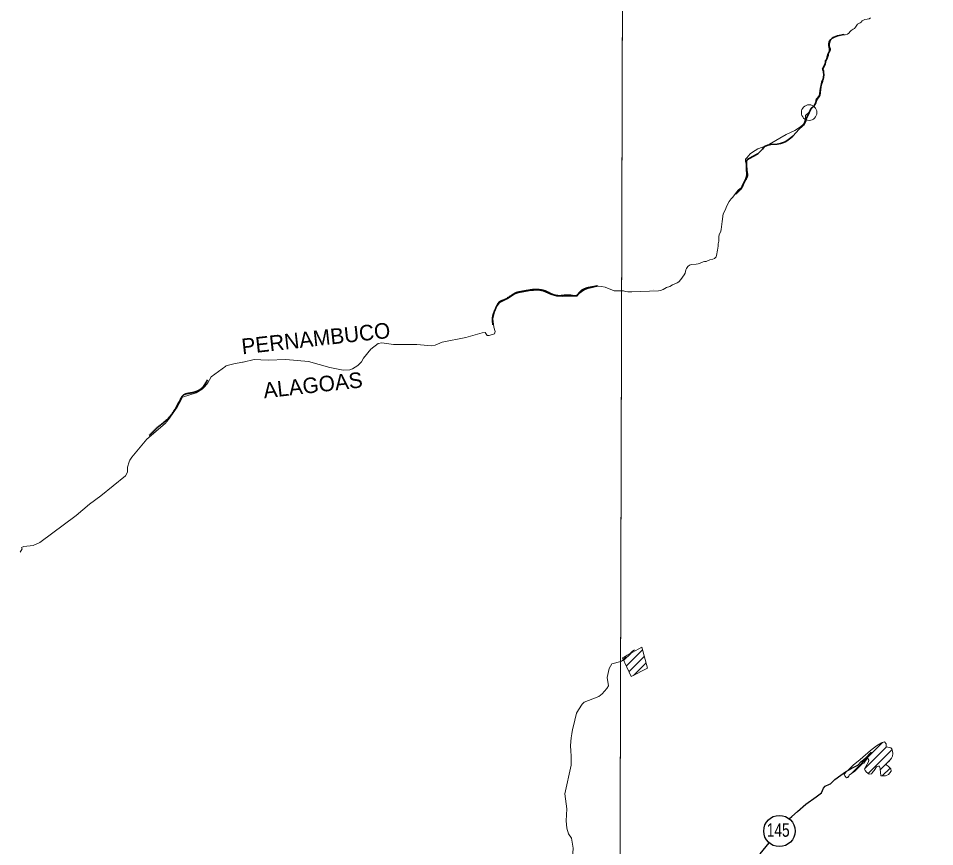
# Model space of a CAD drawing. Extents: x -1643653 to 4543381, y 1624270 to 13878484.
# Drawn here: x 582541 to 587242, y 8914739 to 8918990 of the extents above; entities that cross this region are included whole.
import ezdxf
from ezdxf.enums import TextEntityAlignment as Align

# ---------------------------------------------------------------- set-up
doc = ezdxf.new("R2010")
doc.units = 0
doc.header["$LTSCALE"] = 160
doc.header["$PDMODE"] = 32
doc.header["$PDSIZE"] = 80
doc.linetypes.add('LONG_DASH_SHORT_DASH', pattern=[9.9, 6, -1.2, 1.5, -1.2])
doc.layers.add('6', color=7, linetype='Continuous', lineweight=13)
doc.layers.add('60', color=7, linetype='Continuous', lineweight=13)

msp = doc.modelspace()

# ---------------------------------------------------------------- linework, layer by layer
at = {"layer": '6', "linetype": 'LONG_DASH_SHORT_DASH', "lineweight": 35}
msp.add_line((585799, 8917597.9), (585799.3, 8917597.8), dxfattribs=at)
at = {"layer": '6'}
for p, q in [((585646.2, 8915694.7), (585684.3, 8915732.9)), ((585659.8, 8915665.9), (585742.7, 8915748.8)), ((585654.5, 8915713.5), (585659, 8915718.1)), ((585673.4, 8915637.1), (585751.8, 8915715.5)), ((585696.2, 8915617.4), (585761, 8915682.2)), ((586813.8, 8915113.8), (586974.3, 8915274.2)), ((586882.8, 8915140.3), (586994.4, 8915251.9)), ((586900.1, 8915115.2), (587023, 8915238.1)), ((586961.6, 8915134.2), (587014.3, 8915187)), ((586972, 8915102.2), (587012.5, 8915142.8)), ((586794.2, 8915094.1), (586800.9, 8915100.8))]:
    msp.add_line(p, q, dxfattribs=at)
for points in [[(585656.3, 8924738.8), (585614.8, 8909969.8), (585573.6, 8896026.7)], [(586679.6, 8918760.5), (586680.3, 8918772.5), (586692.5, 8918786.5), (586696.8, 8918798.9), (586696.9, 8918809.3), (586697.7, 8918812.7), (586699.3, 8918815.3), (586704.2, 8918820.1), (586707.7, 8918826.9), (586707.4, 8918834.5), (586702.6, 8918847.7), (586701.8, 8918857.5), (586703.1, 8918864.1), (586709.7, 8918881.3), (586721, 8918893.5), (586725.9, 8918895.7), (586766.1, 8918904.9), (586782.2, 8918905.1), (586794.3, 8918909.1), (586801.8, 8918914.7), (586808.8, 8918923.3), (586813, 8918927.3), (586824.3, 8918933.9), (586830.1, 8918938.5), (586834.8, 8918944.1), (586841.9, 8918955.9), (586845.8, 8918960.3), (586848.8, 8918962.4), (586859.7, 8918966.8), (586863.7, 8918970.4), (586869.3, 8918977.4), (586877.2, 8918981.7), (586883.6, 8918984.1), (586895.7, 8918985.2), (586905.7, 8918987.4), (586911.9, 8918992.7)], [(586136.8, 8917879.9), (586143.9, 8917898.3), (586146.5, 8917907.1), (586150.7, 8917947.5), (586156.3, 8917986.5), (586166.2, 8918006.3), (586175.4, 8918028.7), (586186.6, 8918050.1), (586197.8, 8918063.5), (586206.1, 8918071.9), (586225, 8918098.7), (586234.8, 8918109.9), (586249.5, 8918120.5), (586256.8, 8918127.7), (586261.3, 8918135.7), (586262.8, 8918149.5), (586276.3, 8918165.5), (586281.8, 8918176.7), (586282.8, 8918182.3), (586282.8, 8918191.1), (586279.2, 8918209.5), (586279.1, 8918219.3), (586275.1, 8918241.3), (586270.8, 8918255.1), (586270.6, 8918261.3), (586271.5, 8918267.7), (586278.2, 8918274.1), (586295.8, 8918294.9), (586307.4, 8918303.7), (586335.1, 8918320.1), (586377.8, 8918336.7), (586395.1, 8918344.9), (586480.1, 8918393.5), (586505.7, 8918406.7), (586524.1, 8918414.9), (586554, 8918433.1), (586568.4, 8918447.3), (586570.6, 8918451.1), (586575.7, 8918463.9), (586578.3, 8918475.3), (586579.7, 8918491.9), (586595.5, 8918507.3), (586602.8, 8918522.3), (586607.5, 8918529.5), (586619.7, 8918540.1), (586627.3, 8918548.9), (586630.1, 8918555.5), (586632.3, 8918569.5), (586634.1, 8918575.1), (586636.7, 8918579.5), (586645.9, 8918589.1), (586648.8, 8918594.9), (586650.6, 8918604.3), (586653.5, 8918631.7), (586658.1, 8918644.7), (586665.3, 8918659.3), (586672.6, 8918692.7), (586672.6, 8918710.3), (586671.1, 8918715.7), (586665.9, 8918726.3), (586666, 8918731.5), (586668, 8918736.7), (586678.5, 8918755.1), (586678.5, 8918755.1), (586679.6, 8918760.5)], [(585824.4, 8917592.5), (585835.6, 8917593.5), (585848.5, 8917598.3), (585866.6, 8917609.5), (585883, 8917614.7), (585896.8, 8917622.9), (585921, 8917633.3), (585928.7, 8917638.5), (585940.3, 8917649.7), (585947.5, 8917662.7), (585957.1, 8917673.5), (585961.2, 8917682.5), (585965.9, 8917699.7), (585968.9, 8917706.9), (585976, 8917717.1), (585984.1, 8917723.9), (585988.6, 8917725.7), (585994.5, 8917727.1), (586017.6, 8917728.5), (586028.1, 8917729.9), (586035.3, 8917731.9), (586054, 8917741.3), (586060.6, 8917742.5), (586070, 8917742.7), (586088.9, 8917750.3), (586104.1, 8917754.3), (586112.5, 8917757.7), (586118, 8917762.1), (586120.7, 8917766.5), (586122.9, 8917773.1), (586126.9, 8917800.7), (586130.7, 8917821.1), (586131.4, 8917832.3), (586133.7, 8917846.3), (586134.3, 8917870.5), (586136.8, 8917879.9)], [(585406.5, 8917564.6), (585417.5, 8917578), (585441.3, 8917595.2), (585463.8, 8917604.5), (585514.8, 8917615.6), (585533.1, 8917613.4)], [(585533.1, 8917613.4), (585551.5, 8917611.2), (585597.6, 8917591.8)], [(584946, 8917362.1), (584956.7, 8917362.1), (584984.5, 8917371.3), (584987.1, 8917382.3), (584980.7, 8917404.5), (584974.8, 8917448.6), (584983.7, 8917481.7), (584998.1, 8917514.8), (585010.1, 8917531), (585049.8, 8917550.4), (585085.7, 8917573.9), (585106.9, 8917582), (585162.1, 8917591.8), (585206.3, 8917594.7), (585224.1, 8917592.2)], [(585224.1, 8917592.2), (585233.4, 8917590.9), (585273.5, 8917573.1), (585302.3, 8917565), (585331.2, 8917562.9), (585406.5, 8917564.6)], [(585597.6, 8917591.8), (585645.8, 8917591.3), (585655.1, 8917588.7), (585668.4, 8917587.5), (585687.5, 8917587.3), (585824.4, 8917592.5)], [(584562.5, 8917316.2), (584584.8, 8917316), (584661, 8917309.7), (584679.6, 8917312.2), (584715.2, 8917328.8), (584836.7, 8917352.1), (584920.8, 8917375.9), (584935.7, 8917377.6), (584946, 8917362.1)], [(584289.7, 8917215.3), (584302.2, 8917227.5), (584311.2, 8917245.5), (584349.8, 8917291.8), (584386.3, 8917322.1), (584405.1, 8917324.1), (584466.3, 8917316.9), (584511.8, 8917316.6), (584562.5, 8917316.2)], [(583694.7, 8917225.9), (583751.3, 8917239.9), (583784.8, 8917238.2)], [(583784.8, 8917238.2), (583823, 8917236.2), (583913.9, 8917240), (584030.3, 8917229.4), (584139.1, 8917197.5), (584207.1, 8917184.8), (584241.1, 8917186), (584254.7, 8917190.7), (584281.9, 8917207.8), (584289.7, 8917215.3)], [(583497.2, 8917101.5), (583513.7, 8917119.7), (583530.7, 8917150.3), (583605.6, 8917205.9)], [(583605.6, 8917205.9), (583606.2, 8917206.4), (583647.1, 8917217.9), (583691.7, 8917225.1), (583694.7, 8917225.9)], [(583374.4, 8917029.3), (583384.1, 8917046.7), (583454.1, 8917069.1), (583484.8, 8917087.9), (583497.2, 8917101.5)], [(583110.2, 8916714.5), (583112.9, 8916723.3), (583122.7, 8916738.7), (583200.6, 8916830.8), (583293.7, 8916911.2), (583311.9, 8916931.1), (583355.3, 8916994.9), (583374.4, 8917029.3)], [(583090.8, 8916642.8), (583100.4, 8916661.6), (583101.2, 8916686.4), (583110.2, 8916714.5)], [(582550.9, 8916251), (582561.6, 8916267.1), (582557.7, 8916274.2), (582569.7, 8916279), (582618.1, 8916284.9), (582650.7, 8916300), (582838.2, 8916439.2), (582906.1, 8916497.3), (582963.8, 8916539.2), (583090.8, 8916642.8)], [(585659.6, 8915718.8), (585664, 8915721.8), (585674.1, 8915726.3), (585679.1, 8915730.6), (585692.1, 8915742.6), (585701, 8915749.9)], [(585414.9, 8915441.5), (585432.8, 8915470.1), (585444.4, 8915480.8), (585518.2, 8915510), (585536, 8915523.2), (585560.6, 8915550.4), (585569.1, 8915565.3), (585561.9, 8915607.2), (585571.5, 8915653.5), (585585.9, 8915678), (585631.7, 8915689.4), (585634.6, 8915690.8), (585639.6, 8915694.9), (585655.2, 8915714.2)], [(585387.2, 8915353.3), (585404.3, 8915424.6), (585414.9, 8915441.5)], [(585376.5, 8915206.1), (585374.8, 8915228.7), (585374.3, 8915258.9), (585377.8, 8915297.1), (585380.9, 8915318.6), (585384.2, 8915340.2), (585387.2, 8915353.3)], [(585344.3, 8915010.4), (585377.6, 8915157), (585377.3, 8915185), (585376.5, 8915206.1)], [(585258.2, 8914437.7), (585330, 8914503.1), (585362.7, 8914553.7), (585373.3, 8914579.2), (585378.8, 8914604.6), (585387.7, 8914732), (585378.4, 8914783.1), (585363.1, 8914804.4), (585355, 8914834.1), (585351.6, 8914872.3), (585354.6, 8914933.5), (585344.3, 8915010.4)]]:
    msp.add_lwpolyline(points, dxfattribs=at)
for points in [[(585645.8, 8921027.3), (574684.9, 8921064.7), (574653.9, 8910009.3), (585614.8, 8909969.8)], [(585640, 8915707.7), (585685.4, 8915611.8), (585768.3, 8915655.4), (585738.6, 8915763.7)], [(586913.1, 8915233.4), (586943.5, 8915256), (586968, 8915272.7), (586983.7, 8915276.6), (586992.5, 8915266.8), (586993.5, 8915252.1), (587016, 8915247.2), (587021.9, 8915241.3), (587025.8, 8915229.5), (587026.8, 8915216.8), (587024.8, 8915203), (587019.9, 8915194.2), (587006.2, 8915176.6), (586997.4, 8915168.7), (586993.5, 8915159.9), (587003.3, 8915152), (587016, 8915139.3), (587018, 8915127.5), (587005.2, 8915109.9), (586989.5, 8915102), (586973.9, 8915102), (586965, 8915103), (586961.1, 8915138.3), (586958.2, 8915153), (586953.3, 8915153), (586943.5, 8915149.1), (586931.7, 8915130.5), (586925.8, 8915124.6), (586922.9, 8915119.7), (586918, 8915113.8), (586906.2, 8915110.8), (586892.5, 8915120.7), (586884.6, 8915130.5), (586881.7, 8915138.3), (586901.3, 8915174.6), (586903.3, 8915182.4), (586899.3, 8915192.2), (586894.4, 8915190.3), (586877.8, 8915167.7), (586870.9, 8915165.8), (586832.7, 8915126.5), (586802.3, 8915105.9), (586799.3, 8915095.2), (586789.5, 8915093.2), (586780.7, 8915102), (586777.8, 8915110.8), (586790.5, 8915127.5), (586797.4, 8915131.4), (586823.8, 8915156.9), (586860.1, 8915186.4)]]:
    msp.add_lwpolyline(points, close=True, dxfattribs=at)
at = {"layer": '6', "linetype": 'LONG_DASH_SHORT_DASH', "lineweight": 35}
for points in [[(586698.2, 8918860.5), (586699.5, 8918868.4), (586701.6, 8918872.3), (586709.1, 8918881.7), (586716.2, 8918889), (586725.8, 8918894.1), (586735.2, 8918897.5), (586743.7, 8918899.7), (586775.5, 8918907)], [(586597.6, 8918506.7), (586605.9, 8918523.4), (586611.9, 8918529.9), (586617.3, 8918534), (586622.3, 8918538.9), (586623.4, 8918540.9), (586626.4, 8918548.8), (586631.3, 8918557.1), (586634.3, 8918565.1), (586637.8, 8918573), (586643.9, 8918581.7), (586648.8, 8918589.4), (586652.3, 8918595.6), (586654.7, 8918605.5), (586654.8, 8918613.8), (586656.7, 8918622.1), (586657.8, 8918638.2), (586659.7, 8918646.3), (586661, 8918654.2), (586663.5, 8918662.4), (586666.6, 8918670.9), (586668.9, 8918678.8), (586672.1, 8918687.1), (586672.3, 8918702.8), (586672, 8918712), (586671, 8918719.4), (586667.1, 8918727.6), (586666.9, 8918728.6), (586672.8, 8918742), (586679.1, 8918756), (586680.9, 8918764.7), (586683.4, 8918772.6), (586688.5, 8918781.8), (586690.3, 8918790.4), (586695.8, 8918807.9), (586701.3, 8918821.4), (586701.6, 8918825.4), (586701.4, 8918834.4), (586699.1, 8918851.1), (586698.2, 8918860.5)], [(586513.5, 8918384.7), (586547.2, 8918421.3), (586562.5, 8918435.2), (586568.8, 8918442), (586573.9, 8918450.3), (586577.2, 8918457.8), (586580, 8918465.9), (586583.2, 8918474), (586594.1, 8918498), (586597.6, 8918506.7)], [(586222.6, 8918087.9), (586223.9, 8918090.1), (586228.4, 8918096.1), (586236.5, 8918103.6), (586243.8, 8918110.9), (586250.2, 8918118.5), (586254.6, 8918126.4), (586260.8, 8918142.7), (586268.8, 8918158.2), (586272.8, 8918166.7), (586277.2, 8918183.1), (586278.1, 8918191.2), (586277.5, 8918199.5), (586276, 8918207.8), (586276, 8918223.7), (586276.6, 8918240), (586275.8, 8918254), (586276.7, 8918256.6), (586280.2, 8918263.9), (586287.4, 8918268.9), (586293.9, 8918272.7), (586327.8, 8918291.2), (586334.7, 8918295.4), (586343.5, 8918302.7), (586357.8, 8918319.5), (586363.1, 8918326.4), (586369.2, 8918332), (586377.3, 8918336.3), (586385.6, 8918339.6), (586393.6, 8918341.5), (586401.5, 8918342.9), (586433.8, 8918344.2), (586442.3, 8918345.8), (586450.6, 8918348.2), (586466.5, 8918353.8), (586474.8, 8918357.3), (586483.3, 8918361.6), (586490.3, 8918366.2), (586504.2, 8918377.5), (586513.5, 8918384.7)]]:
    msp.add_lwpolyline(points, dxfattribs=at)
at = {"layer": '6', "lineweight": 25}
for points in [[(586706.4, 8915062.2), (586729.7, 8915084), (586760.1, 8915106.5), (586784.3, 8915123.2), (586823.6, 8915145.7), (586847, 8915158.3), (586863.6, 8915174), (586876.8, 8915185.2), (586890.9, 8915196.4), (586914.5, 8915221.7), (586915.6, 8915222.3), (586917.4, 8915222.5)], [(586497.7, 8914883.6), (586508.3, 8914893.6), (586538, 8914920.3), (586580.2, 8914956.6), (586633.3, 8914995.3), (586661.6, 8915016), (586666.2, 8915026.8), (586670.9, 8915039.1), (586680.2, 8915050.5), (586702.7, 8915060.1), (586706.4, 8915062.2)], [(586228.4, 8914563.8), (586338, 8914686.4), (586347.1, 8914702.6), (586393.3, 8914758.1)]]:
    msp.add_lwpolyline(points, dxfattribs=at)
msp.add_circle((586445.1, 8914819.6), 80.3, dxfattribs=at)
at = {"layer": '6', "linetype": 'LONG_DASH_SHORT_DASH', "lineweight": 35}
for points in [[(585320.8, 8917565.9), (585379.6, 8917568.1), (585403.9, 8917567.3), (585406.1, 8917568.8), (585417.5, 8917582.4), (585451.2, 8917604.6), (585489.2, 8917612.5), (585512.1, 8917617.4)], [(584975.9, 8917417.5), (584975.5, 8917419.7), (584973.4, 8917450.5), (584981.3, 8917482.8), (584997.8, 8917518.6), (585007.8, 8917534.4), (585031.4, 8917545.1), (585065.1, 8917565.2), (585093, 8917581.7), (585131, 8917589.6), (585175.4, 8917597.4), (585208.4, 8917598.2), (585232.7, 8917594.6), (585252.1, 8917588.1), (585282.1, 8917573.1), (585320.8, 8917565.9)], [(583212.7, 8916848.6), (583254.2, 8916889.7), (583303.2, 8916930.2), (583370.6, 8917031.5), (583385.8, 8917055.2), (583431.4, 8917068.7), (583482, 8917092.3), (583511.3, 8917134.2)]]:
    msp.add_spline(points, degree=3, dxfattribs=at)
at = {"layer": '6'}
msp.add_point((586597.6, 8918506.7), dxfattribs=at)
at = {"layer": '60', "lineweight": 25}
msp.add_spline([(814781, 9009175.5), (814787.2, 9009173.4), (814796.9, 9009173.4), (814799.4, 9009172.4), (814805.1, 9009174.5), (814805.6, 9009176.5), (814811.7, 9009179.5), (814811.7, 9009179.5), (814801.5, 9009181), (814790.7, 9009181.5), (814784.1, 9009183.1), (814777.4, 9009185.1), (814778.4, 9009175.5)], degree=3, dxfattribs=at)

# ---------------------------------------------------------------- texts
at = {"layer": '6'}
for s, p in [('PERNAMBUCO', (584071.7, 8917308.3)), ('ALAGOAS', (584056.6, 8917068.5))]:
    msp.add_text(s, height=80, rotation=6.379, dxfattribs=at).set_placement(p, align=Align.CENTER)
at = {"layer": '6', "width": 0.75}
msp.add_text('145', height=70, dxfattribs=at).set_placement((586439, 8914789.8), align=Align.CENTER)

doc.saveas('drawing.dxf')
